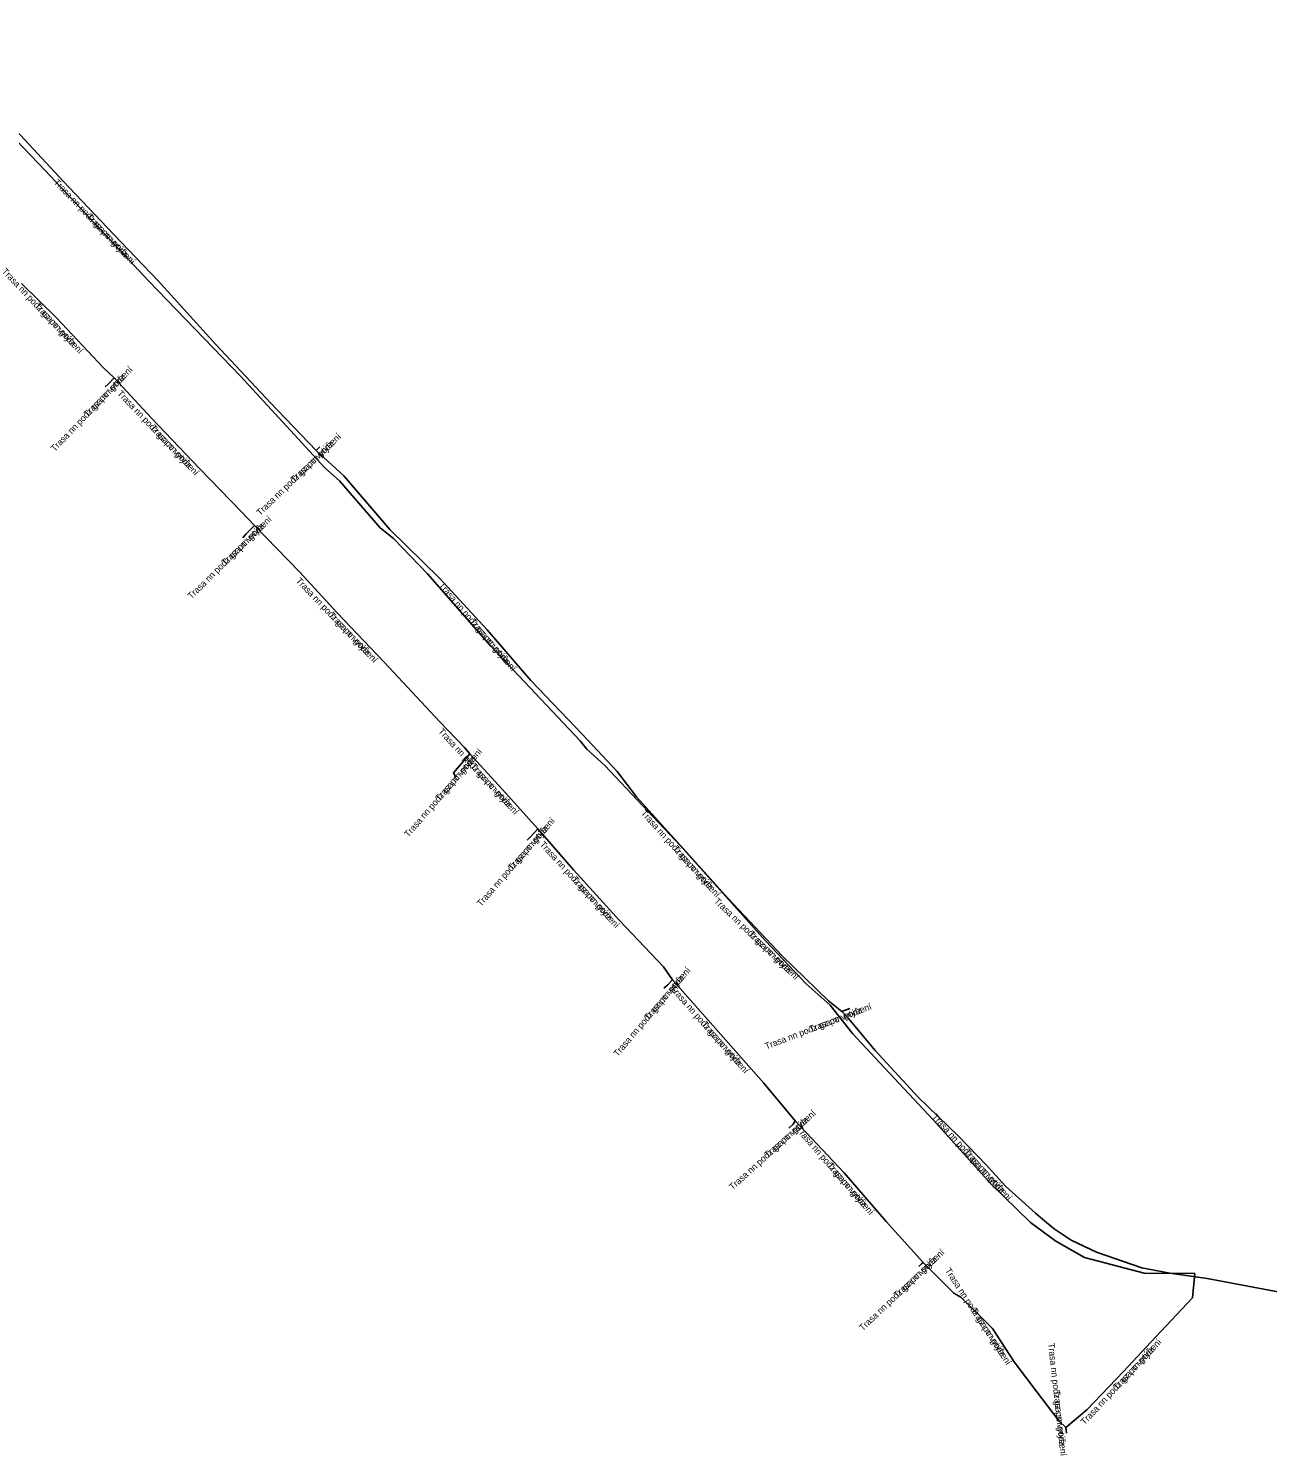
# Model space of a CAD drawing. Extents: x -703240 to -702678, y -1007635 to -1007322.
# Drawn here: x -703052.5 to -702956.7, y -1007635.3 to -1007525 of the extents above; entities that cross this region are included whole.
import ezdxf

# ---------------------------------------------------------------- set-up
doc = ezdxf.new("R2010")
doc.units = 0
for name, color, linetype in [('Popiskový text - Ostatní atributy Trasy', 7, 'Continuous'), ('Spojnice NN', 7, 'Continuous'), ('Spojnice VN', 7, 'Continuous')]:
    doc.layers.add(name, color=color, linetype=linetype)

msp = doc.modelspace()

# ---------------------------------------------------------------- linework, layer by layer
at = {"layer": 'Spojnice NN'}
for points in [[(-703060.24, -1007524.97), (-703057.82, -1007527.9), (-703053.76, -1007532.5), (-703049.79, -1007536.76), (-703045.88, -1007540.85), (-703042.43, -1007544.47), (-703037.97, -1007549.38), (-703033.75, -1007553.9), (-703030.23, -1007557.57)], [(-703060.24, -1007524.97), (-703057.82, -1007527.9), (-703053.76, -1007532.5), (-703049.79, -1007536.76), (-703045.88, -1007540.85), (-703042.43, -1007544.47), (-703037.97, -1007549.38), (-703033.75, -1007553.9), (-703030.23, -1007557.57)], [(-703045.83, -1007551.96), (-703046.67, -1007551.19), (-703050.31, -1007547.33), (-703053.01, -1007544.68)], [(-703045.83, -1007551.96), (-703046.67, -1007551.19), (-703050.31, -1007547.33), (-703053.01, -1007544.68)], [(-703045.83, -1007551.96), (-703046.27, -1007552.42), (-703046.53, -1007552.66)], [(-703045.83, -1007551.96), (-703046.27, -1007552.42), (-703046.53, -1007552.66)], [(-703034.99, -1007563.38), (-703036.02, -1007562.3), (-703039.24, -1007558.98), (-703042.95, -1007555.09), (-703045.83, -1007551.96)], [(-703034.99, -1007563.38), (-703036.02, -1007562.3), (-703039.24, -1007558.98), (-703042.95, -1007555.09), (-703045.83, -1007551.96)], [(-703030.23, -1007557.57), (-703029.95, -1007557.3)], [(-703030.23, -1007557.57), (-703029.95, -1007557.3)], [(-703030.23, -1007557.57), (-703028.09, -1007559.55), (-703024.54, -1007563.7), (-703020.66, -1007567.47), (-703017, -1007571.45), (-703013.64, -1007575.37), (-703009.63, -1007579.52), (-703006.95, -1007582.39), (-703005.47, -1007584.36), (-703001.83, -1007588.37)], [(-703030.23, -1007557.57), (-703028.09, -1007559.55), (-703024.54, -1007563.7), (-703020.66, -1007567.47), (-703017, -1007571.45), (-703013.64, -1007575.37), (-703009.63, -1007579.52), (-703006.95, -1007582.39), (-703005.47, -1007584.36), (-703001.83, -1007588.37)], [(-703034.99, -1007563.38), (-703035.66, -1007564.04), (-703035.9, -1007564.33)], [(-703034.99, -1007563.38), (-703035.66, -1007564.04), (-703035.9, -1007564.33)], [(-703018.36, -1007581.03), (-703018.75, -1007580.53), (-703020.67, -1007578.54), (-703024.96, -1007573.94), (-703028.6, -1007570.13), (-703031.51, -1007566.96), (-703034.99, -1007563.38)], [(-703018.36, -1007581.03), (-703018.75, -1007580.53), (-703020.67, -1007578.54), (-703024.96, -1007573.94), (-703028.6, -1007570.13), (-703031.51, -1007566.96), (-703034.99, -1007563.38)], [(-703018.36, -1007581.03), (-703019.62, -1007582.49), (-703019.42, -1007582.83)], [(-703018.36, -1007581.03), (-703019.62, -1007582.49), (-703019.42, -1007582.83)], [(-703013.1, -1007586.82), (-703015.58, -1007584.05), (-703018.36, -1007581.03)], [(-703013.1, -1007586.82), (-703015.58, -1007584.05), (-703018.36, -1007581.03)], [(-703013.1, -1007586.82), (-703013.62, -1007587.42), (-703013.92, -1007587.7)], [(-703013.1, -1007586.82), (-703013.62, -1007587.42), (-703013.92, -1007587.7)], [(-703002.69, -1007598.48), (-703003.38, -1007597.5), (-703006.79, -1007593.9), (-703010.34, -1007589.99), (-703013.1, -1007586.82)], [(-703002.69, -1007598.48), (-703003.38, -1007597.5), (-703006.79, -1007593.9), (-703010.34, -1007589.99), (-703013.1, -1007586.82)], [(-703001.83, -1007588.37), (-702998.38, -1007592.21)], [(-703001.83, -1007588.37), (-702998.38, -1007592.21)], [(-702998.38, -1007592.21), (-702994.21, -1007596.65), (-702990.61, -1007600.11), (-702989.58, -1007600.94)], [(-702998.38, -1007592.21), (-702994.21, -1007596.65), (-702990.61, -1007600.11), (-702989.58, -1007600.94)], [(-703002.69, -1007598.48), (-703003.03, -1007598.88), (-703003.34, -1007599.13)], [(-703002.69, -1007598.48), (-703003.03, -1007598.88), (-703003.34, -1007599.13)], [(-702993.19, -1007609.39), (-702995.62, -1007606.47), (-702999.14, -1007602.48), (-703002.69, -1007598.48)], [(-702993.19, -1007609.39), (-702995.62, -1007606.47), (-702999.14, -1007602.48), (-703002.69, -1007598.48)], [(-702989.58, -1007600.94), (-702988.98, -1007600.71)], [(-702989.58, -1007600.94), (-702988.98, -1007600.71)], [(-702989.58, -1007600.94), (-702989.07, -1007601.48), (-702987.02, -1007603.95), (-702983.7, -1007607.55), (-702980.6, -1007610.56), (-702978.43, -1007612.79), (-702976.93, -1007614.43), (-702974.61, -1007616.52), (-702974.08, -1007616.98), (-702973.18, -1007617.74), (-702971.86, -1007618.62), (-702969.9, -1007619.53), (-702966.39, -1007620.74), (-702964.24, -1007621.16), (-702962.31, -1007621.18)], [(-702989.58, -1007600.94), (-702989.07, -1007601.48), (-702987.02, -1007603.95), (-702983.7, -1007607.55), (-702980.6, -1007610.56), (-702978.43, -1007612.79), (-702976.93, -1007614.43), (-702974.61, -1007616.52), (-702974.08, -1007616.98), (-702973.18, -1007617.74), (-702971.86, -1007618.62), (-702969.9, -1007619.53), (-702966.39, -1007620.74), (-702964.24, -1007621.16), (-702962.31, -1007621.18)], [(-702993.19, -1007609.39), (-702993.36, -1007609.65), (-702993.69, -1007609.95)], [(-702993.19, -1007609.39), (-702993.36, -1007609.65), (-702993.69, -1007609.95)], [(-702983.3, -1007620.33), (-702986.16, -1007617.18), (-702989.42, -1007613.42), (-702993.19, -1007609.39)], [(-702983.3, -1007620.33), (-702986.16, -1007617.18), (-702989.42, -1007613.42), (-702993.19, -1007609.39)], [(-702983.3, -1007620.33), (-702983.43, -1007620.45), (-702983.63, -1007620.64)], [(-702983.3, -1007620.33), (-702983.43, -1007620.45), (-702983.63, -1007620.64)], [(-702983.3, -1007620.33), (-702980.94, -1007622.72), (-702980.4, -1007623.02), (-702977.95, -1007625.45), (-702976.28, -1007628.02), (-702974.51, -1007630.33), (-702972.8, -1007632.61), (-702972.27, -1007633.09)], [(-702983.3, -1007620.33), (-702980.94, -1007622.72), (-702980.4, -1007623.02), (-702977.95, -1007625.45), (-702976.28, -1007628.02), (-702974.51, -1007630.33), (-702972.8, -1007632.61), (-702972.27, -1007633.09)], [(-702972.27, -1007633.09), (-702970.66, -1007631.72), (-702967.83, -1007628.77), (-702965.35, -1007626.11), (-702962.49, -1007623.08), (-702962.31, -1007621.18)], [(-702972.27, -1007633.09), (-702970.66, -1007631.72), (-702967.83, -1007628.77), (-702965.35, -1007626.11), (-702962.49, -1007623.08), (-702962.31, -1007621.18)], [(-702972.27, -1007633.09), (-702972.22, -1007633.54)], [(-702972.27, -1007633.09), (-702972.22, -1007633.54)]]:
    msp.add_lwpolyline(points, dxfattribs=at)
at = {"layer": 'Spojnice VN'}
msp.add_lwpolyline([(-702953, -1007623.14), (-702961.34, -1007621.58), (-702964.06, -1007621.2), (-702966.23, -1007621.16), (-702970.83, -1007619.94), (-702973.06, -1007618.68), (-702975.01, -1007617.26), (-702978.08, -1007614.26), (-702982.53, -1007609.3), (-702987.01, -1007604.53), (-702988.78, -1007602.63), (-702990.5, -1007600.44), (-702992.34, -1007598.79), (-702995.48, -1007595.48), (-703001.18, -1007589.12), (-703002.1, -1007588.1), (-703007.92, -1007581.92), (-703009.31, -1007580.66), (-703009.81, -1007580.01), (-703016.72, -1007572.71), (-703021.61, -1007567.12), (-703024.24, -1007564.39), (-703025.27, -1007563.57), (-703028.42, -1007559.92), (-703029.56, -1007558.91), (-703036.05, -1007551.87), (-703043.19, -1007544.46), (-703051.16, -1007535.96), (-703055.1, -1007531.88)], dxfattribs=at)

# ---------------------------------------------------------------- texts
at = {"layer": 'Popiskový text - Ostatní atributy Trasy'}
for s, rotation, p in [('Trasa nn podz gz po vytýèení', 313.6226, (-703050.55, -1007536.89)), ('Trasa nn podz', 313.6226, (-703048.01, -1007539.56)), ('Trasa nn podz gz po vytýèení', 313.3198, (-703054.56, -1007543.77)), ('Trasa nn podz', 313.3198, (-703052.03, -1007546.45)), ('Trasa nn podz gz po vytýèení', 46.273, (-703050.43, -1007557.7)), ('Trasa nn podz', 46.273, (-703047.88, -1007555.04)), ('Trasa nn podz gz po vytýèení', 313.6432, (-703045.64, -1007553.21)), ('Trasa nn podz', 313.6432, (-703043.09, -1007555.88)), ('Trasa nn podz gz po vytýèení', 43.9584, (-703034.56, -1007562.65)), ('Trasa nn podz', 43.9584, (-703031.9, -1007560.09)), ('Trasa nn podz gz po vytýèení', 44.5692, (-703039.87, -1007569.1)), ('Trasa nn podz', 44.5692, (-703037.24, -1007566.51)), ('Trasa nn podz gz po vytýèení', 313.6928, (-703031.83, -1007567.69)), ('Trasa nn podz gz po vytýèení', 310.6013, (-703020.79, -1007568.03)), ('Trasa nn podz', 313.6928, (-703029.29, -1007570.35)), ('Trasa nn podz', 310.6013, (-703018.39, -1007570.83)), ('Trasa nn podz gz po vytýèení', 312.6305, (-703020.82, -1007579.32)), ('Trasa nn podz gz po vytýèení', 49.2054, (-703023.09, -1007587.51)), ('Trasa nn podz', 49.2054, (-703020.68, -1007584.72)), ('Trasa nn podz', 312.6305, (-703018.32, -1007582.03)), ('Trasa nn podz gz po vytýèení', 311.9377, (-703005.16, -1007585.64)), ('Trasa nn podz gz po vytýèení', 49.0856, (-703017.48, -1007592.86)), ('Trasa nn podz', 49.0856, (-703015.06, -1007590.08)), ('Trasa nn podz gz po vytýèení', 312.2372, (-703012.98, -1007588.05)), ('Trasa nn podz', 311.9377, (-703002.69, -1007588.38)), ('Trasa nn podz', 312.2372, (-703010.5, -1007590.77)), ('Trasa nn podz gz po vytýèení', 316.136, (-702999.51, -1007592.46)), ('Trasa nn podz', 316.136, (-702996.85, -1007595.02)), ('Trasa nn podz gz po vytýèení', 49.6355, (-703006.92, -1007604.46)), ('Trasa nn podz', 49.6355, (-703004.53, -1007601.65)), ('Trasa nn podz gz po vytýèení', 311.4189, (-703002.9, -1007599.2)), ('Trasa nn podz gz po vytýèení', 20.9735, (-702995.43, -1007603.88)), ('Trasa nn podz', 20.9735, (-702991.99, -1007602.56)), ('Trasa nn podz', 311.4189, (-703000.46, -1007601.96)), ('Trasa nn podz gz po vytýèení', 42.2737, (-702998.03, -1007614.77)), ('Trasa nn podz gz po vytýèení', 312.4471, (-702982.67, -1007609.12)), ('Trasa nn podz', 42.2737, (-702995.3, -1007612.29)), ('Trasa nn podz gz po vytýèení', 310.926, (-702993.17, -1007610.09)), ('Trasa nn podz', 312.4471, (-702980.18, -1007611.84)), ('Trasa nn podz', 310.926, (-702990.76, -1007612.87)), ('Trasa nn podz gz po vytýèení', 43.5312, (-702987.97, -1007625.66)), ('Trasa nn podz', 43.5312, (-702985.3, -1007623.12)), ('Trasa nn podz gz po vytýèení', 303.016, (-702981.64, -1007620.96)), ('Trasa nn podz', 303.016, (-702979.63, -1007624.05)), ('Trasa nn podz gz po vytýèení', 47.0056, (-702970.82, -1007632.93)), ('Trasa nn podz gz po vytýèení', 276.3402, (-702973.65, -1007626.6)), ('Trasa nn podz', 47.0056, (-702968.3, -1007630.23)), ('Trasa nn podz', 276.3402, (-702973.24, -1007630.26))]:
    msp.add_text(s, height=0.5, rotation=rotation, dxfattribs=at).set_placement(p)

doc.saveas('drawing.dxf')
